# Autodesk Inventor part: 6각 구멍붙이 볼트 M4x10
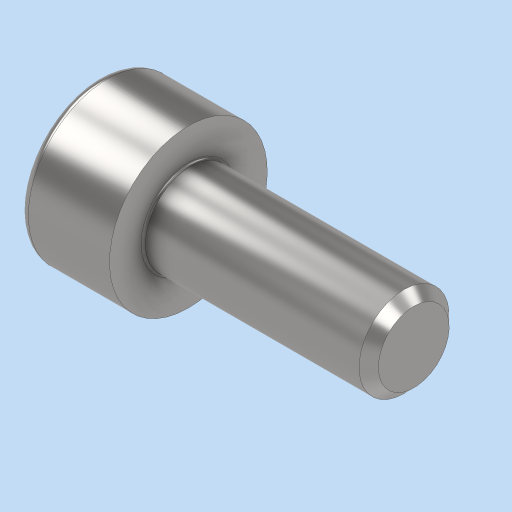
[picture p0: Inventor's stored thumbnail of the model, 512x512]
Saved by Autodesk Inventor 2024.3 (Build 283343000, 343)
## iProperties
Created: 2026-01
Part Number: 6각 구멍붙이 볼트 M4x10
Material: 강철, 연강
Description: 6각머리 태핑 나사
Document SubType Name: Modeling
Designer: PC2-02
Density: 7.85 g/cm^3
Appearance: 기본값
Author: jhkim
Sending System: Autodesk Inventor 2026
Preprocessor: ST-DEVELOPER v20.1
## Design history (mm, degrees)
node "6각 구멍붙이 볼트 M4x101"
node "솔리드1"
body "Solid1"
